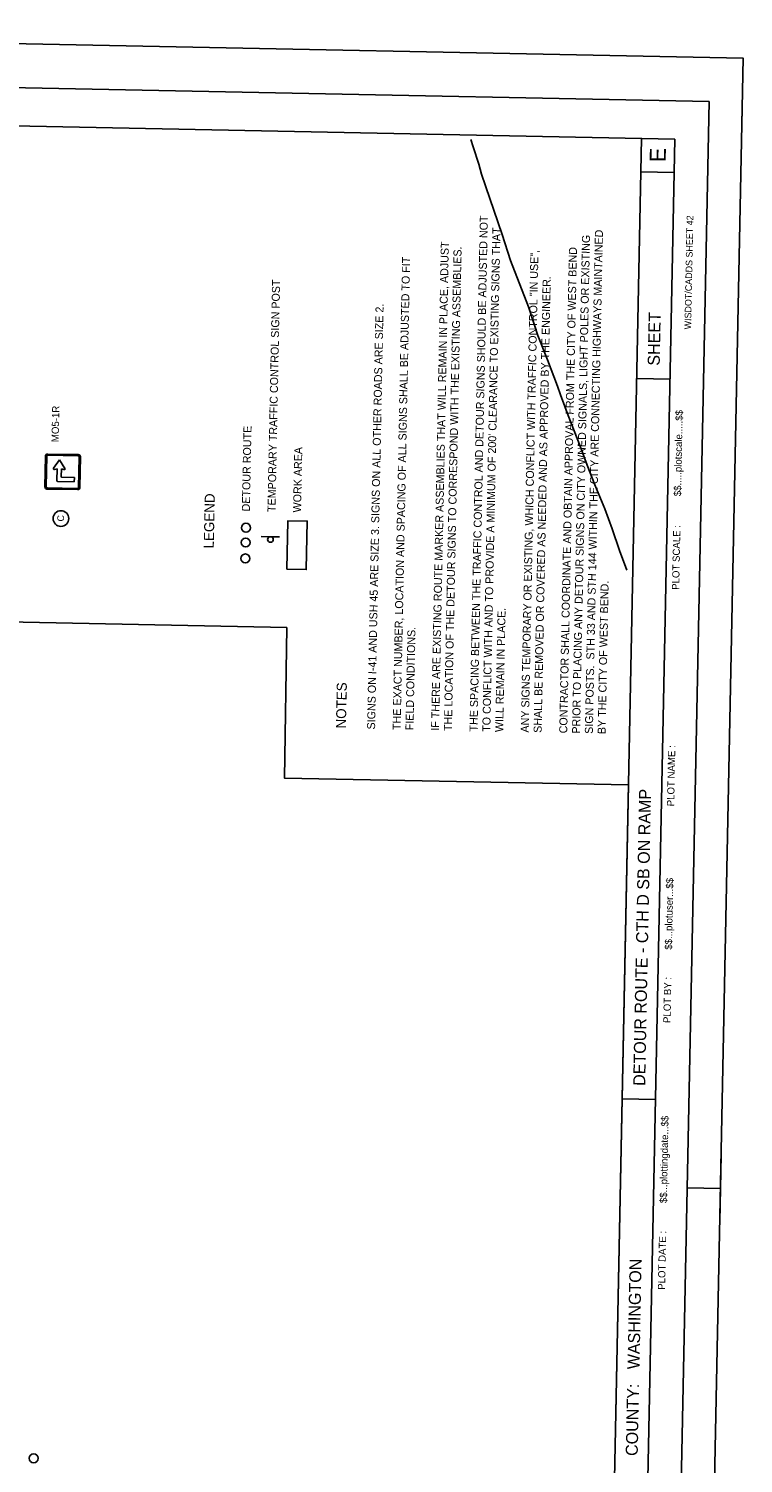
# Model space of a CAD drawing. Extents: x 327762 to 372975, y 127949 to 220470.
# Drawn here: x 359592 to 372975, y 193585 to 220470 of the extents above; entities that cross this region are included whole.
import ezdxf

# ---------------------------------------------------------------- set-up
doc = ezdxf.new("R2010")
doc.units = 0
for name, color, linetype in [('CA-TEXT', 7, 'Continuous'), ('CE-TOPO-CONC-SLAB', 7, 'Continuous'), ('GSBWFILL', 7, 'Continuous'), ('GSCOLORFILL', 7, 'Continuous'), ('Level 1', 7, 'Continuous'), ('P_SGN_Cell', 7, 'Continuous'), ('P_TC', 7, 'Continuous'), ('PLT_Sheet_Border', 7, 'Continuous'), ('PLT_Sheet_Info', 7, 'Continuous'), ('SIGNS-POLES', 7, 'Continuous')]:
    doc.layers.add(name, color=color, linetype=linetype)

msp = doc.modelspace()

# ---------------------------------------------------------------- linework, layer by layer
at = {"layer": 'CA-TEXT'}
msp.add_circle((360195, 211290), 147, dxfattribs=at)
at = {"layer": 'CE-TOPO-CONC-SLAB'}
for centre in [(363660, 211117), (363655, 210841), (363649, 210542), (359685, 193678)]:
    msp.add_circle(centre, 83.7, dxfattribs=at)
at = {"layer": 'GSBWFILL'}
msp.add_lwpolyline([(344626, 177980), (345482, 220470), (372975, 219916), (372119, 177427)], close=True, dxfattribs=at)
at = {"layer": 'GSCOLORFILL'}
msp.add_lwpolyline([(345907, 179536), (346513, 209608), (364425, 209247), (364381, 206427), (370825, 206298), (370277, 179045)], close=True, dxfattribs=at)
at = {"layer": 'Level 1'}
for points in [[(369125, 214721), (368954, 215257), (368618, 216124), (368456, 216616), (368070, 217744), (368020, 217932), (367919, 218256), (367872, 218391)], [(370658, 210691), (370521, 211097), (370379, 211473), (370195, 211923), (370053, 212289), (369921, 212644), (369697, 213219), (369554, 213606), (369493, 213773), (369310, 214264), (369125, 214721)], [(370791, 210323), (370658, 210691)]]:
    msp.add_lwpolyline(points, dxfattribs=at)
at = {"layer": 'P_SGN_Cell'}
for p, q in [((359894, 211885), (359905, 212459)), ((359916, 212459), (359905, 211885)), ((359930, 212459), (359918, 211885)), ((359947, 212499), (360521, 212488)), ((360521, 212477), (359947, 212488)), ((360521, 212463), (359947, 212475)), ((360537, 212446), (360525, 211872)), ((360550, 212446), (360539, 211872)), ((360561, 212446), (360550, 211872)), ((360166, 212388), (360057, 212236)), ((360074, 212210), (360122, 212224)), ((360122, 212224), (360117, 212001)), ((360270, 212231), (360166, 212388)), ((360201, 212078), (360204, 212222)), ((360204, 212222), (360251, 212207)), ((360508, 211856), (359934, 211868)), ((360134, 211984), (360445, 211978)), ((360447, 212060), (360214, 212065)), ((360445, 211978), (360447, 212060)), ((360508, 211843), (359934, 211854)), ((360508, 211832), (359934, 211843))]:
    msp.add_line(p, q, dxfattribs=at)
for centre, radius, start, end in [((359946, 212458), 41, 88.8462, 178.8462), ((359946, 212458), 30.1, 88.8462, 178.8462), ((359946, 212458), 16.4, 88.8462, 178.8462), ((360520, 212447), 41, 358.8462, 88.8462), ((360520, 212447), 30.1, 358.8462, 88.8462), ((360520, 212447), 16.4, 358.8462, 88.8462), ((360070, 212226), 16.4, 144.3166, 285.6488), ((360256, 212222), 16.4, 252.0436, 33.3759), ((359935, 211884), 41, 178.8462, 268.8462), ((359935, 211884), 30.1, 178.8462, 268.8462), ((359935, 211884), 16.4, 178.8462, 268.8462), ((360134, 212001), 16.4, 178.8462, 268.8462), ((360215, 212078), 13.7, 178.8462, 268.8462), ((360509, 211873), 16.4, 268.8462, 358.8462), ((360509, 211873), 30.1, 268.8462, 358.8462), ((360509, 211873), 41, 268.8462, 358.8462)]:
    msp.add_arc(centre, radius, start, end, dxfattribs=at)
at = {"layer": 'P_TC'}
msp.add_lwpolyline([(364427, 210341), (364445, 211250), (364808, 211243), (364789, 210334)], close=True, dxfattribs=at)
at = {"layer": 'PLT_Sheet_Border'}
for points in [[(372119, 177427), (372975, 219916), (345482, 220470), (344626, 177980)], [(371500, 177739), (372334, 219104), (346090, 219633), (345257, 178268)]]:
    msp.add_lwpolyline(points, close=True, dxfattribs=at)
at = {"layer": 'PLT_Sheet_Info'}
for p, q in [((372975, 219916), (371725, 219942)), ((372950, 218667), (372975, 219916)), ((371694, 218398), (346700, 218902)), ((370277, 179045), (371069, 218411)), ((370901, 179033), (371694, 218398)), ((371682, 217773), (371057, 217786)), ((371604, 213899), (370979, 213912)), ((371332, 200403), (370707, 200415)), ((372536, 198109), (372561, 199359)), ((372548, 198734), (371924, 198746))]:
    msp.add_line(p, q, dxfattribs=at)
at = {"layer": 'SIGNS-POLES'}
for p, q in [((363947, 210951), (364116, 210950)), ((364117, 210949), (364286, 210947))]:
    msp.add_line(p, q, dxfattribs=at)
msp.add_circle((364119, 210897), 52.2, dxfattribs=at)

# ---------------------------------------------------------------- texts
at = {"layer": 'CA-TEXT'}
for s, height, rotation, p in [('THE SPACING BETWEEN THE TRAFFIC CONTROL AND DETOUR SIGNS SHOULD BE ADJUSTED NOT', 149.99, 88.8462, (367997, 207297)), ("TO CONFLICT WITH AND TO PROVIDE A MINIMUM OF 200' CLEARANCE TO EXISTING SIGNS THAT", 149.99, 88.8462, (368237, 207292)), ('IF THERE ARE EXISTING ROUTE MARKER ASSEMBLIES THAT WILL REMAIN IN PLACE, ADJUST', 149.99, 88.8462, (367277, 207312)), ('PRIOR TO PLACING ANY DETOUR SIGNS ON CITY OWNED SIGNALS, LIGHT POLES OR EXISTING', 149.99, 88.8462, (369917, 207258)), ('SIGN POSTS.  STH 33 AND STH 144 WITHIN THE CITY ARE CONNECTING HIGHWAYS MAINTAINED ', 149.99, 88.8462, (370157, 207254)), ('THE EXACT NUMBER, LOCATION AND SPACING OF ALL SIGNS SHALL BE ADJUSTED TO FIT', 149.99, 88.8462, (366557, 207326)), ('THE LOCATION OF THE DETOUR SIGNS TO CORRESPOND WITH THE EXISTING ASSEMBLIES. ', 149.99, 88.8462, (367517, 207307)), ('ANY SIGNS TEMPORARY OR EXISTING, WHICH CONFLICT WITH TRAFFIC CONTROL "IN USE",', 149.99, 88.8462, (368957, 207278)), ('CONTRACTOR SHALL COORDINATE AND OBTAIN APPROVAL FROM THE CITY OF WEST BEND', 149.99, 88.8462, (369677, 207263)), ('TEMPORARY TRAFFIC CONTROL SIGN POST', 149.99, 88.8468, (364213, 211412)), ('SHALL BE REMOVED OR COVERED AS NEEDED AND AS APPROVED BY THE ENGINEER.', 149.99, 88.8462, (369197, 207273)), ('SIGNS ON I-41 AND USH 45 ARE SIZE 3. SIGNS ON ALL OTHER ROADS ARE SIZE 2.', 149.99, 88.8462, (366078, 207336)), ('DETOUR ROUTE', 149.99, 88.8468, (363733, 211422)), ('WORK AREA', 150, 88.8468, (364692, 211403)), ('LEGEND', 187.5, 88.8468, (363057, 210728)), ('C', 125, 88.8468, (360252, 211234)), ('BY THE CITY OF WEST BEND.', 149.99, 88.8462, (370396, 207249)), ('WILL REMAIN IN PLACE.', 149.99, 88.8462, (368477, 207287)), ('FIELD CONDITIONS.', 149.99, 88.8462, (366797, 207321)), ('NOTES', 187.5, 88.8468, (365533, 207354))]:
    msp.add_text(s, height=height, rotation=rotation, dxfattribs=at).set_placement(p)
at = {"layer": 'P_SGN_Cell'}
msp.add_text('MO5-1R', height=135, rotation=88.8462, dxfattribs=at).set_placement((360153, 212721))
at = {"layer": 'PLT_Sheet_Info'}
for s, height, p in [('E', 300, (371521, 217967)), ('WISDOT/CADDS SHEET 42', 125, (371997, 214834)), ('SHEET ', 225, (371409, 214153)), ('$$.....plotscale.....$$', 134.99, (371809, 211707)), ('PLOT SCALE : ', 134.99, (371774, 209953)), ('PLOT NAME :                      ', 134.99, (371680, 205896)), ('DETOUR ROUTE - CTH D SB ON RAMP', 224.99, (371137, 200656)), ('$$...plotuser...$$', 134.99, (371638, 203209)), ('PLOT BY :', 135, (371611, 201835)), ('$$...plottingdate...$$', 134.99, (371543, 198460)), ('PLOT DATE :', 134.99, (371510, 196836)), ('WASHINGTON            ', 224.99, (371030, 195345)), ('COUNTY:', 225, (370997, 193721))]:
    msp.add_text(s, height=height, rotation=88.8462, dxfattribs=at).set_placement(p)

doc.saveas('drawing.dxf')
